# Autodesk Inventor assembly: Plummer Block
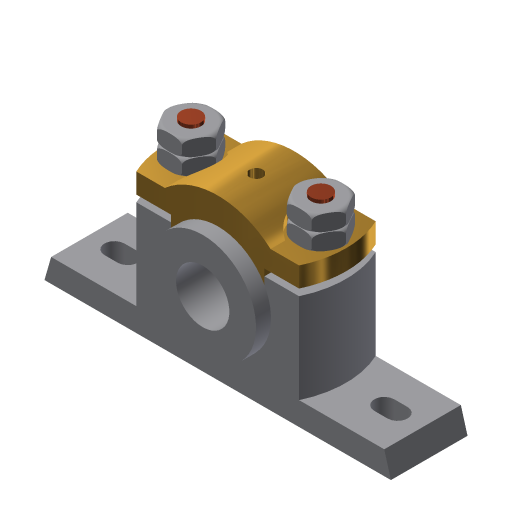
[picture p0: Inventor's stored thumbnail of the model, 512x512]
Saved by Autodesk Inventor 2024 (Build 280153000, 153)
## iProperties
Created: 2011-07
Part Number: Plummer Block
Document SubType Name: Assembly
Designer: CadCim
Author: CadCim
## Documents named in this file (7)
- D:\PROJECTS\Project 2023\RESOURCES INVENTOR 2024\RESOURCES INVENTOR 2024\Inventor_2023_Part\Inventor_2024_Part\c11_Inv_2024_prt\c11_Inv_2024_prt\figure-11-23 through 11-26\Plummer Block.iam
- D:\PROJECTS\Project 2023\RESOURCES INVENTOR 2024\RESOURCES INVENTOR 2024\Inventor_2023_Part\Inventor_2024_Part\c11_Inv_2024_prt\c11_Inv_2024_prt\figure-11-23 through 11-26\Casting.ipt
- D:\PROJECTS\Project 2023\RESOURCES INVENTOR 2024\RESOURCES INVENTOR 2024\Inventor_2023_Part\Inventor_2024_Part\c11_Inv_2024_prt\c11_Inv_2024_prt\figure-11-23 through 11-26\Brasses.ipt
- D:\PROJECTS\Project 2023\RESOURCES INVENTOR 2024\RESOURCES INVENTOR 2024\Inventor_2023_Part\Inventor_2024_Part\c11_Inv_2024_prt\c11_Inv_2024_prt\figure-11-23 through 11-26\Cap.ipt
- D:\PROJECTS\Project 2023\RESOURCES INVENTOR 2024\RESOURCES INVENTOR 2024\Inventor_2023_Part\Inventor_2024_Part\c11_Inv_2024_prt\c11_Inv_2024_prt\figure-11-23 through 11-26\Bolt.ipt
- D:\PROJECTS\Project 2023\RESOURCES INVENTOR 2024\RESOURCES INVENTOR 2024\Inventor_2023_Part\Inventor_2024_Part\c11_Inv_2024_prt\c11_Inv_2024_prt\figure-11-23 through 11-26\Nut.ipt
- D:\PROJECTS\Project 2023\RESOURCES INVENTOR 2024\RESOURCES INVENTOR 2024\Inventor_2023_Part\Inventor_2024_Part\c11_Inv_2024_prt\c11_Inv_2024_prt\figure-11-23 through 11-26\Lock Nut.ipt
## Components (9 placed, 6 different names)
1. Casting:1 — Mate:1, Mate:2, Insert:1, Insert:2, Angle:1, Angle:2
2. Brasses:1 — Mate:1, Mate:2, Mate:3, Mate:4
3. Cap:1 — Mate:3, Mate:4, Insert:3, Insert:4
4. Bolt:1 — Insert:1, Angle:1
5. Bolt:2 — Insert:2, Angle:2
6. Nut:1 — Insert:3, Insert:6
7. Nut:2 — Insert:4, Insert:5
8. Lock Nut:1 — Insert:6
9. Lock Nut:2 — Insert:5
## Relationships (12: Insert 6, Mate 4, Angle 2)
- Mate:1: Casting:1 ↔ Brasses:1
- Mate:2: Casting:1 ↔ Brasses:1
- Mate:3: Brasses:1 ↔ Cap:1
- Mate:4: Brasses:1 ↔ Cap:1
- Insert:1: Casting:1 ↔ Bolt:1
- Insert:2: Casting:1 ↔ Bolt:2
- Angle:1: Casting:1 ↔ Bolt:1
- Angle:2: Casting:1 ↔ Bolt:2
- Insert:3: Cap:1 ↔ Nut:1
- Insert:4: Cap:1 ↔ Nut:2
- Insert:5: Nut:2 ↔ Lock Nut:2
- Insert:6: Nut:1 ↔ Lock Nut:1
